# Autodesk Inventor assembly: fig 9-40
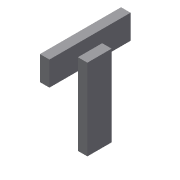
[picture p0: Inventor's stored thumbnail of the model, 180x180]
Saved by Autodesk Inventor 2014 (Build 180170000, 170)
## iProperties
Created: 2013-07
Part Number: fig 9-40
Document SubType Name: Assembly
Designer: CADCIM
Author: CADCIM
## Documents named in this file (2)
- E:\APS\Autodesk Inventor 2014-Project\inventor_2014_partfiles\Inventor_2014_prt\c09_Inv_2014_prt\c09_inv_2014_prt\fig 9-40.iam
- E:\APS\Autodesk Inventor 2014-Project\inventor_2014_partfiles\Inventor_2014_prt\c09_Inv_2014_prt\c09_inv_2014_prt\12.ipt
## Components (2 placed, 1 different names)
1. 12:1 — Rigid:1
2. 12:2 — Rigid:1
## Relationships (1: WeldJoint 1)
- Rigid:1 [WeldJoint]: 12:1 ↔ 12:2
